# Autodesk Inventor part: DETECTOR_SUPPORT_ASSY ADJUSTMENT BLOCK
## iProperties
Shininess: 64.0
Length Units: 11272
Angle Units: 11279
Time Units: 11290
Mass Units: 11286
Length Display Precision: 3
Angle Display Precision: 2
Compacted: True
Part Number: DETECTOR_SUPPORT_ASSY ADJUSTMENT BLOCK
Document SubType Name: Modeling
Created: 2004-08
Designer: John Blackburn
Material: ALUMINUM
Manufacturer: Standard
Standards Organization: Custom
Density: 0.0
Volumn: 0.0
Area: 0.0
PropertySet Name: Model Information
Control State: 0
Master: False
Checked Out: False
Author: John Blackburn
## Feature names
1. ExtrusionBlind1
2. AM_HOLE_SI0030_1 [Hole]
3. Hole1
4. Hole2
